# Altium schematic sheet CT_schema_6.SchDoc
size 278 x 170 mm
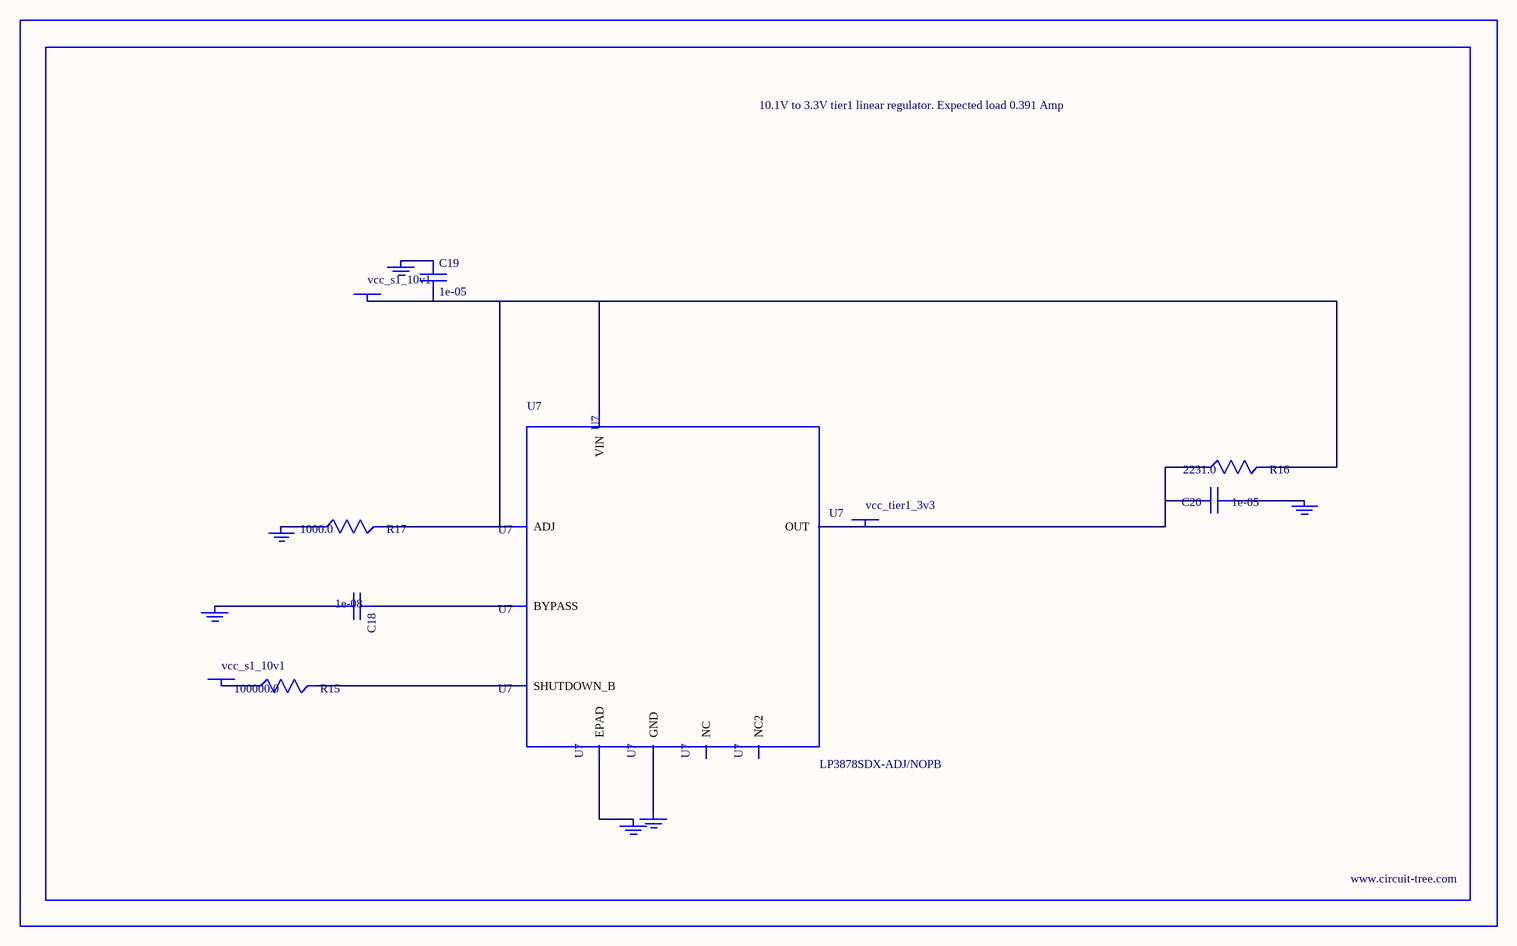
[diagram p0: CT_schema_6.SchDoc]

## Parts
BORDER5  (no value)
C18  1e-08  [C0402]
C19  1e-05  [C1206]
C20  1e-05  [C1210]
GND_INSTANCE_5_0  (no value)
GND_INSTANCE_5_1  (no value)
GND_INSTANCE_5_2  (no value)
GND_INSTANCE_5_3  (no value)
GND_INSTANCE_5_4  (no value)
GND_INSTANCE_5_5  (no value)
POWER_INSTANCE_5_0  vcc_s1_10v1
POWER_INSTANCE_5_1  vcc_s1_10v1
POWER_INSTANCE_5_2  vcc_tier1_3v3
R15  100000.0  [R0603]
R16  2231.0  [R0603]
R17  1000.0  [R0603]
U7  LP3878SDX-ADJ/NOPB  [WSON-8]

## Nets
NetC18_1: C18.1 U7.1(BYPASS)
NetC18_2: C18.2 GND_INSTANCE_5_0.0(GND)
NetC19_1: C19.1 GND_INSTANCE_5_1.0(GND)
NetC19_2: C19.2 POWER_INSTANCE_5_0.0(PWR) R16.2 R17.2 U7.4(VIN) U7.6(ADJ)
NetC20_1: C20.1 GND_INSTANCE_5_2.0(GND)
NetC20_2: C20.2 POWER_INSTANCE_5_2.0(PWR) R16.1 U7.5(OUT)
NetGND_INSTANCE_5_3_0: GND_INSTANCE_5_3.0(GND) R17.1
NetGND_INSTANCE_5_4_0: GND_INSTANCE_5_4.0(GND) U7.PAD(EPAD)
NetGND_INSTANCE_5_5_0: GND_INSTANCE_5_5.0(GND) U7.3(GND)
NetPOWER_INSTANCE_5_1_0: POWER_INSTANCE_5_1.0(PWR) R15.1
NetR15_2: R15.2 U7.8(SHUTDOWN_B)

Not connected (* = marked no-connect by the designer): U7 2(NC) 7(NC2)

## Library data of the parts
BORDER5 = BORDER_PAGE5
C18 = C0402C103K3RAC
C19 = C1206C106K3RACTU
C20 = GRM32DR61E106MA12L
GND_INSTANCE_5_0-GND_INSTANCE_5_5 = GND
POWER_INSTANCE_5_0-POWER_INSTANCE_5_2 = PWR
R15 = RC0603JR-07100KL
R16 = R16
R17 = RC0603JR-071KL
